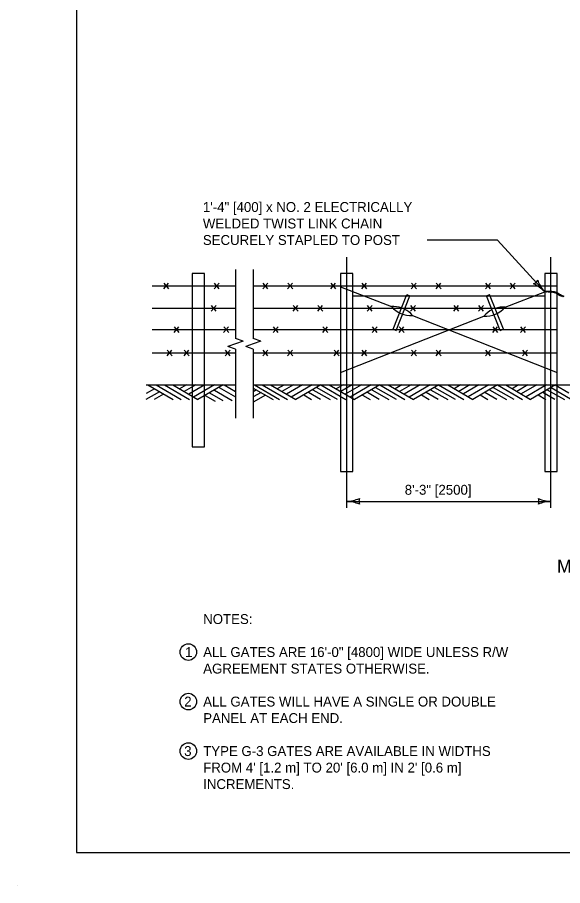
# Model space of a CAD drawing. Extents: x 49991.4 to 50021, y 49987.6 to 50011.4.
# Drawn here: x 49999.98 to 50003.28, y 49999.86 to 50005.12 of the extents above; entities that cross this region are included whole.
import ezdxf

# ---------------------------------------------------------------- set-up
doc = ezdxf.new("R2010")
doc.units = 0
for name, color, linetype in [('Level 1', 7, 'Continuous'), ('Level 2', 7, 'Continuous'), ('Level 3', 7, 'Continuous'), ('Level 4', 7, 'Continuous'), ('Level 5', 7, 'Continuous'), ('Level 6', 7, 'Continuous')]:
    doc.layers.add(name, color=color, linetype=linetype)

msp = doc.modelspace()

# ---------------------------------------------------------------- linework, layer by layer
at = {"layer": 'Level 1'}
for p, q in [((50001.0369, 50003.5711), (50001.0369, 50002.8961)), ((50001.1119, 50003.5711), (50001.0369, 50003.5711)), ((50001.1119, 50002.8961), (50001.1119, 50003.5711)), ((50001.9369, 50003.5711), (50001.9369, 50002.8961)), ((50002.0119, 50003.5711), (50001.9369, 50003.5711)), ((50002.0119, 50002.8961), (50002.0119, 50003.5711)), ((50003.2494, 50003.5711), (50003.1744, 50003.5711)), ((50003.1744, 50003.5711), (50003.1744, 50002.8961)), ((50003.2494, 50002.8961), (50003.2494, 50003.5711)), ((50000.8646, 50003.478), (50000.894, 50003.5127)), ((50000.8953, 50003.478), (50000.866, 50003.5127)), ((50001.17, 50003.478), (50001.1994, 50003.5127)), ((50001.2007, 50003.478), (50001.1714, 50003.5127)), ((50001.4654, 50003.478), (50001.4948, 50003.5127)), ((50001.4961, 50003.478), (50001.4668, 50003.5127)), ((50001.6154, 50003.478), (50001.6448, 50003.5127)), ((50001.6461, 50003.478), (50001.6168, 50003.5127)), ((50001.8774, 50003.478), (50001.9068, 50003.5127)), ((50001.9081, 50003.478), (50001.8788, 50003.5127)), ((50002.0654, 50003.478), (50002.0948, 50003.5127)), ((50002.0961, 50003.478), (50002.0668, 50003.5127)), ((50002.3654, 50003.478), (50002.3948, 50003.5127)), ((50002.3961, 50003.478), (50002.3668, 50003.5127)), ((50002.5154, 50003.478), (50002.5448, 50003.5127)), ((50002.5461, 50003.478), (50002.5168, 50003.5127)), ((50002.8154, 50003.478), (50002.8448, 50003.5127)), ((50002.8461, 50003.478), (50002.8168, 50003.5127)), ((50002.9654, 50003.478), (50002.9948, 50003.5127)), ((50002.9961, 50003.478), (50002.9668, 50003.5127)), ((50000.7938, 50003.4961), (50001.2994, 50003.4961)), ((50001.4073, 50003.4961), (50003.2494, 50003.4961)), ((50001.9369, 50003.4906), (50002.245, 50003.3719)), ((50002.0119, 50003.4961), (50003.1744, 50003.4961)), ((50002.9343, 50003.3684), (50003.1744, 50003.4609)), ((50002.0119, 50003.4361), (50003.1744, 50003.4361)), ((50002.2549, 50003.2345), (50002.3381, 50003.4445)), ((50002.2735, 50003.2271), (50002.3567, 50003.4371)), ((50002.3381, 50003.4445), (50002.3567, 50003.4371)), ((50002.8219, 50003.4371), (50002.8405, 50003.4445)), ((50002.9051, 50003.2271), (50002.8219, 50003.4371)), ((50002.9237, 50003.2345), (50002.8405, 50003.4445)), ((50000.7938, 50003.3611), (50001.2994, 50003.3611)), ((50001.1525, 50003.343), (50001.1818, 50003.3777)), ((50001.1832, 50003.343), (50001.1538, 50003.3777)), ((50001.4073, 50003.3611), (50003.2494, 50003.3611)), ((50001.6483, 50003.343), (50001.6776, 50003.3777)), ((50001.679, 50003.343), (50001.6496, 50003.3777)), ((50001.7983, 50003.343), (50001.8276, 50003.3777)), ((50001.829, 50003.343), (50001.7996, 50003.3777)), ((50002.0983, 50003.343), (50002.1276, 50003.3777)), ((50002.129, 50003.343), (50002.0996, 50003.3777)), ((50002.3608, 50003.343), (50002.3901, 50003.3777)), ((50002.3915, 50003.343), (50002.3621, 50003.3777)), ((50002.6233, 50003.343), (50002.6526, 50003.3777)), ((50002.654, 50003.343), (50002.6246, 50003.3777)), ((50002.7733, 50003.343), (50002.8026, 50003.3777)), ((50002.804, 50003.343), (50002.7746, 50003.3777)), ((50001.9369, 50002.9711), (50002.8059, 50003.3133)), ((50002.3735, 50003.3168), (50003.2494, 50002.9711)), ((50000.9275, 50003.214), (50000.9568, 50003.2487)), ((50000.9582, 50003.214), (50000.9288, 50003.2487)), ((50001.2275, 50003.214), (50001.2568, 50003.2487)), ((50001.2582, 50003.214), (50001.2288, 50003.2487)), ((50001.5283, 50003.214), (50001.5576, 50003.2487)), ((50001.559, 50003.214), (50001.5296, 50003.2487)), ((50001.8283, 50003.214), (50001.8576, 50003.2487)), ((50001.859, 50003.214), (50001.8296, 50003.2487)), ((50002.1283, 50003.214), (50002.1576, 50003.2487)), ((50002.159, 50003.214), (50002.1296, 50003.2487)), ((50002.2915, 50003.214), (50002.3208, 50003.2487)), ((50002.3222, 50003.214), (50002.2928, 50003.2487)), ((50002.8598, 50003.214), (50002.8891, 50003.2487)), ((50002.8905, 50003.214), (50002.8611, 50003.2487)), ((50003.0283, 50003.214), (50003.0576, 50003.2487)), ((50003.059, 50003.214), (50003.0296, 50003.2487)), ((50000.7938, 50003.2321), (50001.2994, 50003.2321)), ((50001.4073, 50003.2321), (50003.2494, 50003.2321)), ((50002.2549, 50003.2345), (50002.2735, 50003.2271)), ((50002.9051, 50003.2271), (50002.9237, 50003.2345)), ((50000.7938, 50003.0911), (50001.2994, 50003.0911)), ((50000.8846, 50003.073), (50000.914, 50003.1077)), ((50000.9153, 50003.073), (50000.886, 50003.1077)), ((50000.9874, 50003.073), (50001.0168, 50003.1077)), ((50001.0181, 50003.073), (50000.9888, 50003.1077)), ((50001.2374, 50003.073), (50001.2668, 50003.1077)), ((50001.2681, 50003.073), (50001.2388, 50003.1077)), ((50001.4073, 50003.0911), (50003.2494, 50003.0911)), ((50001.4654, 50003.073), (50001.4948, 50003.1077)), ((50001.4961, 50003.073), (50001.4668, 50003.1077)), ((50001.6154, 50003.073), (50001.6448, 50003.1077)), ((50001.6461, 50003.073), (50001.6168, 50003.1077)), ((50001.8971, 50003.073), (50001.9265, 50003.1077)), ((50001.9278, 50003.073), (50001.8985, 50003.1077)), ((50002.0654, 50003.073), (50002.0948, 50003.1077)), ((50002.0961, 50003.073), (50002.0668, 50003.1077)), ((50002.3654, 50003.073), (50002.3948, 50003.1077)), ((50002.3961, 50003.073), (50002.3668, 50003.1077)), ((50002.5154, 50003.073), (50002.5448, 50003.1077)), ((50002.5461, 50003.073), (50002.5168, 50003.1077)), ((50002.8154, 50003.073), (50002.8448, 50003.1077)), ((50002.8461, 50003.073), (50002.8168, 50003.1077)), ((50003.0404, 50003.073), (50003.0698, 50003.1077)), ((50003.0711, 50003.073), (50003.0418, 50003.1077)), ((50000.7586, 50002.8961), (50001.2994, 50002.8961)), ((50000.7686, 50002.8961), (50000.9208, 50002.8082)), ((50000.8186, 50002.8961), (50000.9708, 50002.8082)), ((50000.8686, 50002.8961), (50001.0208, 50002.8082)), ((50000.9186, 50002.8961), (50001.072, 50002.8075)), ((50001.002, 50002.8961), (50000.9603, 50002.872)), ((50001.0581, 50002.8961), (50000.9883, 50002.8559)), ((50001.1133, 50002.8961), (50001.0159, 50002.8399)), ((50001.1724, 50002.8961), (50001.0455, 50002.8228)), ((50001.2254, 50002.8961), (50001.072, 50002.8075)), ((50001.2007, 50002.8818), (50001.2994, 50002.8246)), ((50001.2302, 50002.8961), (50001.2994, 50002.8561)), ((50001.4073, 50002.8961), (50003.2779, 50002.8961)), ((50001.4073, 50002.8778), (50001.5279, 50002.8082)), ((50001.415, 50002.8961), (50001.5672, 50002.8082)), ((50001.462, 50002.8961), (50001.6142, 50002.8082)), ((50001.5111, 50002.8961), (50001.6645, 50002.8075)), ((50001.5916, 50002.8944), (50001.5528, 50002.872)), ((50001.6506, 50002.8961), (50001.5808, 50002.8559)), ((50001.7058, 50002.8961), (50001.6084, 50002.8399)), ((50001.7649, 50002.8961), (50001.638, 50002.8228)), ((50001.8179, 50002.8961), (50001.6645, 50002.8075)), ((50001.7922, 50002.8812), (50001.9165, 50002.8094)), ((50001.8171, 50002.8961), (50001.9693, 50002.8082)), ((50001.8681, 50002.8961), (50002.0215, 50002.8075)), ((50001.9515, 50002.8961), (50001.9098, 50002.872)), ((50002.0076, 50002.8961), (50001.9378, 50002.8559)), ((50002.0628, 50002.8961), (50001.9654, 50002.8399)), ((50002.1219, 50002.8961), (50001.995, 50002.8228)), ((50002.1749, 50002.8961), (50002.0215, 50002.8075)), ((50002.1492, 50002.8812), (50002.2735, 50002.8094)), ((50002.1741, 50002.8961), (50002.3263, 50002.8082)), ((50002.2251, 50002.8961), (50002.3785, 50002.8075)), ((50002.3085, 50002.8961), (50002.2668, 50002.872)), ((50002.3646, 50002.8961), (50002.2948, 50002.8559)), ((50002.4198, 50002.8961), (50002.3224, 50002.8399)), ((50002.4789, 50002.8961), (50002.352, 50002.8228)), ((50002.5319, 50002.8961), (50002.3785, 50002.8075)), ((50002.5062, 50002.8812), (50002.6305, 50002.8094)), ((50002.5311, 50002.8961), (50002.6833, 50002.8082)), ((50002.5872, 50002.8961), (50002.7377, 50002.8092)), ((50002.6647, 50002.8961), (50002.626, 50002.8737)), ((50002.7208, 50002.8961), (50002.6539, 50002.8576)), ((50002.776, 50002.8961), (50002.6816, 50002.8416)), ((50002.8351, 50002.8961), (50002.7112, 50002.8245)), ((50002.8881, 50002.8961), (50002.7377, 50002.8092)), ((50002.8624, 50002.8812), (50002.9867, 50002.8094)), ((50002.8873, 50002.8961), (50003.0395, 50002.8082)), ((50002.9383, 50002.8961), (50003.0888, 50002.8092)), ((50003.0158, 50002.8961), (50002.9771, 50002.8737)), ((50003.0719, 50002.8961), (50003.005, 50002.8576)), ((50003.1271, 50002.8961), (50003.0327, 50002.8416)), ((50003.1862, 50002.8961), (50003.0623, 50002.8245)), ((50003.2392, 50002.8961), (50003.0888, 50002.8092)), ((50003.2135, 50002.8812), (50003.3317, 50002.8129)), ((50003.2384, 50002.8961), (50003.3217, 50002.8479)), ((50003.2779, 50002.8961), (50004.5739, 50002.8961)), ((50000.8387, 50002.8556), (50000.7564, 50002.8082)), ((50000.8079, 50002.8734), (50000.7586, 50002.8449)), ((50000.8633, 50002.8414), (50000.8057, 50002.8082)), ((50001.1161, 50002.833), (50001.1757, 50002.7985)), ((50001.1424, 50002.8482), (50001.2219, 50002.8023)), ((50001.1714, 50002.8649), (50001.2787, 50002.803)), ((50001.427, 50002.8664), (50001.4073, 50002.8551)), ((50001.4544, 50002.8506), (50001.4073, 50002.8235)), ((50001.4817, 50002.8349), (50001.4073, 50002.792)), ((50001.7129, 50002.8355), (50001.76, 50002.8082)), ((50001.7422, 50002.8524), (50001.8144, 50002.8106)), ((50001.7685, 50002.8676), (50001.8725, 50002.8075)), ((50002.0702, 50002.8353), (50002.117, 50002.8082)), ((50002.0992, 50002.8524), (50002.1714, 50002.8106)), ((50002.1255, 50002.8676), (50002.2295, 50002.8075)), ((50002.4269, 50002.8355), (50002.474, 50002.8082)), ((50002.4562, 50002.8524), (50002.5284, 50002.8106)), ((50002.4825, 50002.8676), (50002.5865, 50002.8075)), ((50002.7831, 50002.8355), (50002.8302, 50002.8082)), ((50002.8124, 50002.8524), (50002.8846, 50002.8106)), ((50002.8387, 50002.8676), (50002.9427, 50002.8075)), ((50003.1342, 50002.8355), (50003.1813, 50002.8082)), ((50003.1635, 50002.8524), (50003.2357, 50002.8106)), ((50003.1898, 50002.8676), (50003.2938, 50002.8075)), ((49999.9766, 49999.8624), (49999.9766, 49999.8624))]:
    msp.add_line(p, q, dxfattribs=at)
msp.add_lwpolyline([(50008.6146, 50011.2628), (50000.3356, 50011.2628), (50000.3356, 50000.0624), (50008.6146, 50000.0624)], close=True, dxfattribs=at)
for centre, start, end in [((50002.2547, 50003.2172), 70.692, 93.5951), ((50002.3638, 50003.4716), 220.0078, 273.5951), ((50002.2547, 50003.2172), 40.0078, 63.2871), ((50002.8155, 50003.468), 266.4347, 320.0376), ((50002.9247, 50003.2137), 116.5245, 140.0376), ((50002.9247, 50003.2137), 86.4347, 109.12)]:
    msp.add_arc(centre, 0.155, start, end, dxfattribs=at)
for centre in [(50003.1754, 50003.4622), (50003.182, 50003.4622), (50003.1887, 50003.4625), (50003.197, 50003.4625), (50003.2015, 50003.4611), (50003.2116, 50003.4618), (50003.219, 50003.4604), (50003.2245, 50003.4597), (50003.2298, 50003.4594), (50003.2319, 50003.4587), (50003.2378, 50003.4573), (50003.2413, 50003.4559), (50003.2461, 50003.4545), (50003.2486, 50003.4528), (50003.2521, 50003.4507), (50003.2545, 50003.4489), (50003.2587, 50003.4458), (50003.2618, 50003.4441), (50003.2667, 50003.4416), (50003.2688, 50003.4406), (50003.2723, 50003.4388), (50003.2768, 50003.4368), (50003.2841, 50003.434)]:
    msp.add_ellipse(centre, major_axis=(-0.0053, 0), ratio=0.584906, dxfattribs=at)
at = {"layer": 'Level 2'}
for centre in [(50001.0135, 50001.2777), (50001.0135, 50000.9777), (50001.0135, 50000.6777)]:
    msp.add_circle(centre, 0.0501, dxfattribs=at)
at = {"layer": 'Level 3'}
for p, q in [((50002.8884, 50003.7746), (50002.461, 50003.7746)), ((50003.1708, 50003.4637), (50002.8884, 50003.7746)), ((50001.9744, 50002.1911), (50003.2119, 50002.1911))]:
    msp.add_line(p, q, dxfattribs=at)
for centre, radius, start, end in [((50003.0846, 50003.5586), 0.0548, 294.387, 330.1094), ((50003.0063, 50003.2988), 0.233, 45.0755, 64.3254), ((50003.3414, 50003.6063), 0.2223, 199.7042, 219.8877), ((50001.9629, 50002.4238), 0.233, 272.8273, 292.0772), ((50001.9652, 50001.969), 0.2223, 67.456, 87.6395), ((50002.1026, 50002.1911), 0.0548, 162.1388, 197.8612), ((50003.2211, 50002.4132), 0.2223, 247.456, 267.6395), ((50003.0837, 50002.1911), 0.0548, 342.1388, 17.8612), ((50003.2234, 50001.9584), 0.233, 92.8273, 112.0772)]:
    msp.add_arc(centre, radius, start, end, dxfattribs=at)
at = {"layer": 'Level 4'}
for p, q in [((50001.0369, 50002.8961), (50001.0369, 50002.5211)), ((50001.1119, 50002.5211), (50001.1119, 50002.8961)), ((50001.9369, 50002.8961), (50001.9369, 50002.3711)), ((50002.0119, 50002.3711), (50002.0119, 50002.8961)), ((50003.1744, 50002.8961), (50003.1744, 50002.3711)), ((50003.2494, 50002.3711), (50003.2494, 50002.8961)), ((50001.0369, 50002.5211), (50001.1119, 50002.5211)), ((50001.9369, 50002.3711), (50002.0119, 50002.3711)), ((50003.1744, 50002.3711), (50003.2494, 50002.3711))]:
    msp.add_line(p, q, dxfattribs=at)
at = {"layer": 'Level 5'}
for p, q in [((50001.9744, 50002.1511), (50001.9744, 50003.6711)), ((50003.2119, 50002.1511), (50003.2119, 50003.6711))]:
    msp.add_line(p, q, dxfattribs=at)
at = {"layer": 'Level 6'}
for p, q in [((50001.2994, 50003.5961), (50001.2994, 50003.1785)), ((50001.4073, 50003.5961), (50001.4073, 50003.1785)), ((50001.2994, 50003.1461), (50001.2537, 50003.1299)), ((50001.3451, 50003.1623), (50001.2994, 50003.1785)), ((50001.3451, 50003.1623), (50001.2994, 50003.1461)), ((50001.4073, 50003.1461), (50001.3616, 50003.1299)), ((50001.453, 50003.1623), (50001.4073, 50003.1785)), ((50001.453, 50003.1623), (50001.4073, 50003.1461)), ((50001.2994, 50003.1137), (50001.2537, 50003.1299)), ((50001.2994, 50003.1137), (50001.2994, 50002.6961)), ((50001.4073, 50003.1137), (50001.3616, 50003.1299)), ((50001.4073, 50003.1137), (50001.4073, 50002.6961))]:
    msp.add_line(p, q, dxfattribs=at)

# ---------------------------------------------------------------- texts
at = {"layer": 'Level 2'}
for s, height, p in [('1\'-4" [400] x NO. 2 ELECTRICALLY', 0.06, (50001.1016, 50003.9446)), ('WELDED TWIST LINK CHAIN', 0.06, (50001.1016, 50003.8446)), ('SECURELY STAPLED TO POST', 0.06, (50001.1016, 50003.7446)), ('8\'-3" [2500]', 0.06, (50002.3257, 50002.2311)), ('METAL FARM ENTRANCE GATE (TYPE G-3)', 0.08, (50003.249, 50001.7583)), ('NOTES:', 0.06, (50001.1036, 50001.4477)), ('1', 0.06, (50000.9941, 50001.2477)), ('ALL GATES ARE 16\'-0" [4800] WIDE UNLESS R/W', 0.06, (50001.1036, 50001.2477)), ('AGREEMENT STATES OTHERWISE.', 0.06, (50001.1036, 50001.1477)), ('2', 0.06, (50000.9884, 50000.9477)), ('ALL GATES WILL HAVE A SINGLE OR DOUBLE', 0.06, (50001.1036, 50000.9477)), ('PANEL AT EACH END.', 0.06, (50001.1036, 50000.8477)), ('3', 0.06, (50000.9883, 50000.6477)), ('TYPE G-3 GATES ARE AVAILABLE IN WIDTHS ', 0.06, (50001.1036, 50000.6477)), ("FROM 4' [1.2 m] TO 20' [6.0 m] IN 2' [0.6 m] ", 0.06, (50001.1036, 50000.5477)), ('INCREMENTS.', 0.06, (50001.1036, 50000.4477))]:
    msp.add_text(s, height=height, dxfattribs=at).set_placement(p)

doc.saveas('drawing.dxf')
